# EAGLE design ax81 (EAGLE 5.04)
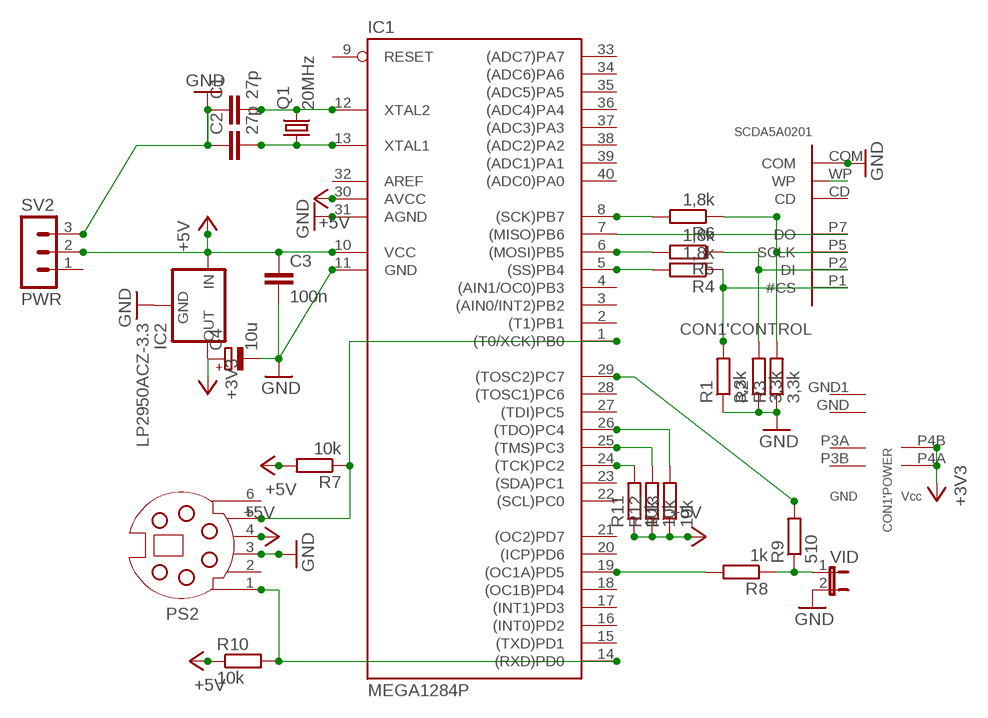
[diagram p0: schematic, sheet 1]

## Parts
C1  27p  C-EU025-025X050  [C025-025X050]
C2  27p  C-EU025-025X050  [C025-025X050]
C3  100n  C-EU025-025X050  [C025-025X050]
C4  10u  CPOL-EUE2.5-5  [E2,5-5]
CON1  SCDA5A0201  [SCDA5A0201]
IC1  MEGA1284P  MEGA32-P  [DIL40]
IC2  LP2950ACZ-3.3  [TO92]
PS2  MDSSV-BC06  [SSV-BC06]
Q1  20MHz  CRYSTALHC49U-V  [HC49U-V]
R1  3,3k  R-EU_0207/7  [0207/7]
R2  3,3k  R-EU_0207/7  [0207/7]
R3  3,3k  R-EU_0207/7  [0207/7]
R4  1,8k  R-EU_0207/7  [0207/7]
R5  1,8k  R-EU_0207/7  [0207/7]
R6  1,8k  R-EU_0207/7  [0207/7]
R7  10k  R-EU_0207/7  [0207/7]
R8  1k  R-EU_0207/7  [0207/7]
R9  510  R-EU_0207/7  [0207/7]
R10  10k  R-EU_0207/7  [0207/7]
R11  10k  R-EU_0207/7  [0207/7]
R12  10k  R-EU_0207/7  [0207/7]
R13  10k  R-EU_0207/7  [0207/7]
SV2  PWR  MA03-1  [MA03-1]
VID  JP1E  [JP1]

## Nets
+3V3: C4.+ CON1.P4A('POWER:VCC) CON1.P4B('POWER:VCC1) IC2.1(OUT)
+5V: C3.1 IC1.10(VCC) IC1.30(AVCC) IC2.3(IN) PS2.4 R7.2 R10.1 R11.1 R12.1 R13.1 SV2.2
GND: C1.1 C2.1 C3.2 C4.- CON1.COM('CONTROL:COM) IC1.11(GND) IC1.31(AGND) IC2.2(GND) PS2.3 R1.1 R2.1 R3.1 SV2.3 VID.2
N$1: C1.2 IC1.12(XTAL2) Q1.2
N$2: C2.2 IC1.13(XTAL1) Q1.1
N$3: IC1.19((OC1A)PD5) R8.2
N$4: IC1.5((SS)PB4) R4.2
N$5: IC1.6((MOSI)PB5) R5.2
N$6: IC1.8((SCK)PB7) R6.2
N$7: CON1.P1('CONTROL:#CS) R1.2 R4.1
N$8: CON1.P7('CONTROL:DO) IC1.7((MISO)PB6)
N$9: CON1.P2('CONTROL:DI) R2.2 R5.1
N$10: R8.1 R9.1 VID.1
N$11: IC1.29((TOSC2)PC7) R9.2
N$12: IC1.14((RXD)PD0) PS2.1 R10.2
N$13: IC1.1((T0/XCK)PB0) PS2.5 R7.1
N$14: IC1.24((TCK)PC2) R11.2
N$15: IC1.25((TMS)PC3) R12.2
N$16: IC1.26((TDO)PC4) R13.2
N$20: CON1.P5('CONTROL:SCLK) R3.2 R6.1
N$24: CON1.WP('CONTROL:WP)
Unconnected: CON1.CD('CONTROL:CD) IC1.2((T1)PB1) IC1.3((AIN0/INT2)PB2) IC1.4((AIN1/OC0)PB3) IC1.9(RESET) IC1.15((TXD)PD1) IC1.16((INT0)PD2) IC1.17((INT1)PD3) IC1.18((OC1B)PD4) IC1.20((ICP)PD6) IC1.21((OC2)PD7) IC1.22((SCL)PC0) IC1.23((SDA)PC1) IC1.27((TDI)PC5) IC1.28((TOSC1)PC6) IC1.32(AREF) IC1.33((ADC7)PA7) IC1.34((ADC6)PA6) IC1.35((ADC5)PA5) IC1.36((ADC4)PA4) IC1.37((ADC3)PA3) IC1.38((ADC2)PA2) IC1.39((ADC1)PA1) IC1.40((ADC0)PA0) PS2.2 PS2.6 SV2.1

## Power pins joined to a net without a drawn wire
GND: CON1.GND1('POWER:GND) CON1.GND('POWER:GND) CON1.P3A('POWER:GND) CON1.P3B('POWER:GND)

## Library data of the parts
C1-C3 = rcl:C-EU: CAPACITOR, European symbol
C4 = rcl:CPOL-EU: POLARIZED CAPACITOR, European symbol
CON1 = SCDA5A0201:SCDA5A0201: ALPS Connector for SDMemory Card SD-CARD SCDA5A0201 SPI -MODE
IC1 = atmel:MEGA32-P: MICROCONTROLLER 32 Kbytes FLASH 2 Kbytes SRAM 1 Kbytes EEPROM USART 8-channel 10 bit ADC Source: www.atmel.com .. doc2503.pdf
IC2 = v-reg:LP2950?*: Source: http://cache.national.com/ds/LP/LP2950.pdf
PS2 = con-yamaichi:MDSSV-BC06: YAMAICHI CONNECTOR
Q1 = crystal:CRYSTAL: CRYSTAL
R1-R13 = rcl:R-EU_: RESISTOR, European symbol
SV2 = con-lstb:MA03-1: PIN HEADER
VID = jumper:JP1E: JUMPER

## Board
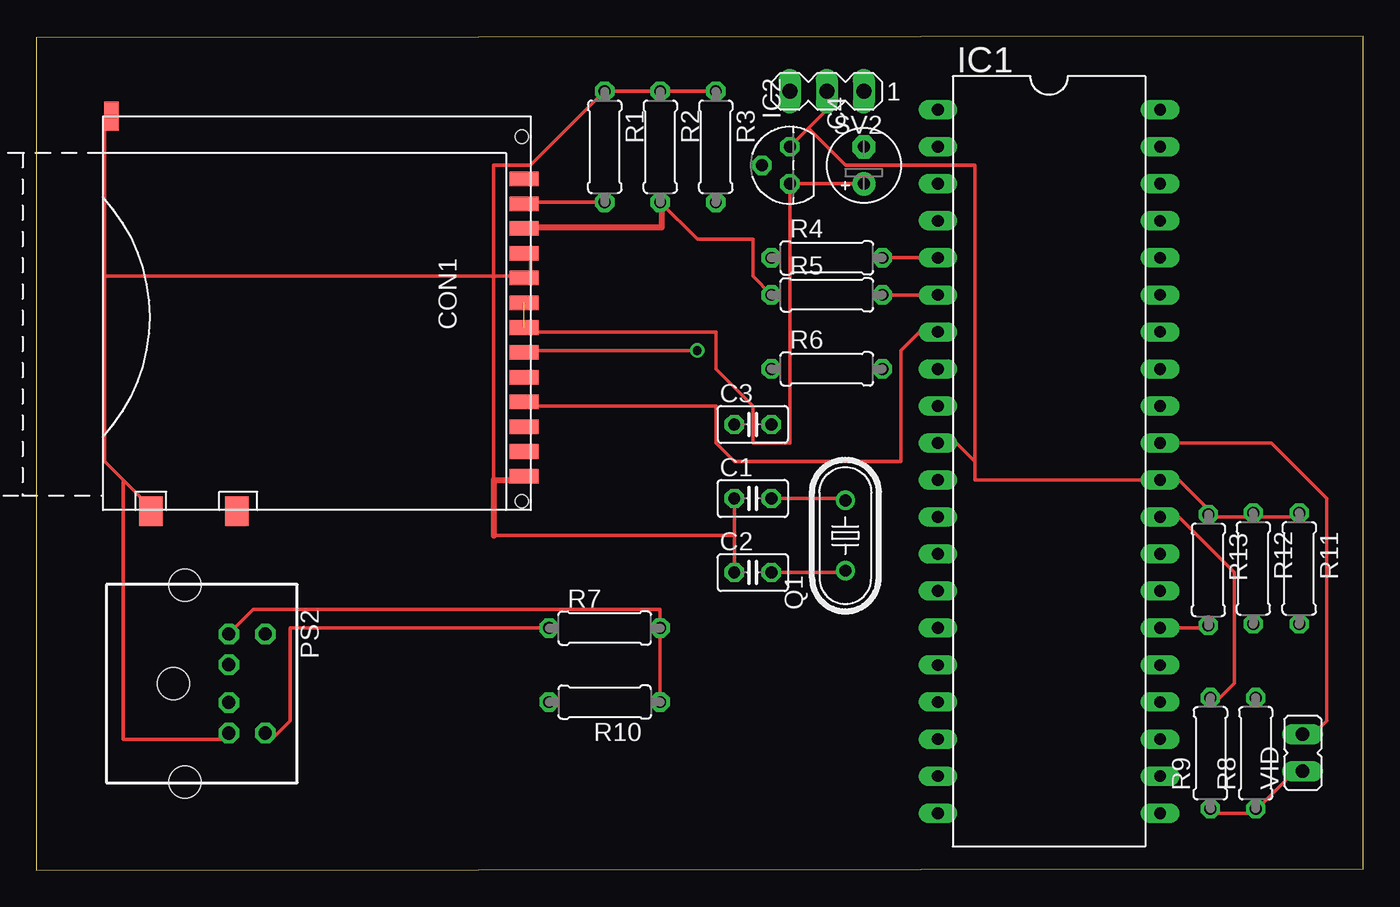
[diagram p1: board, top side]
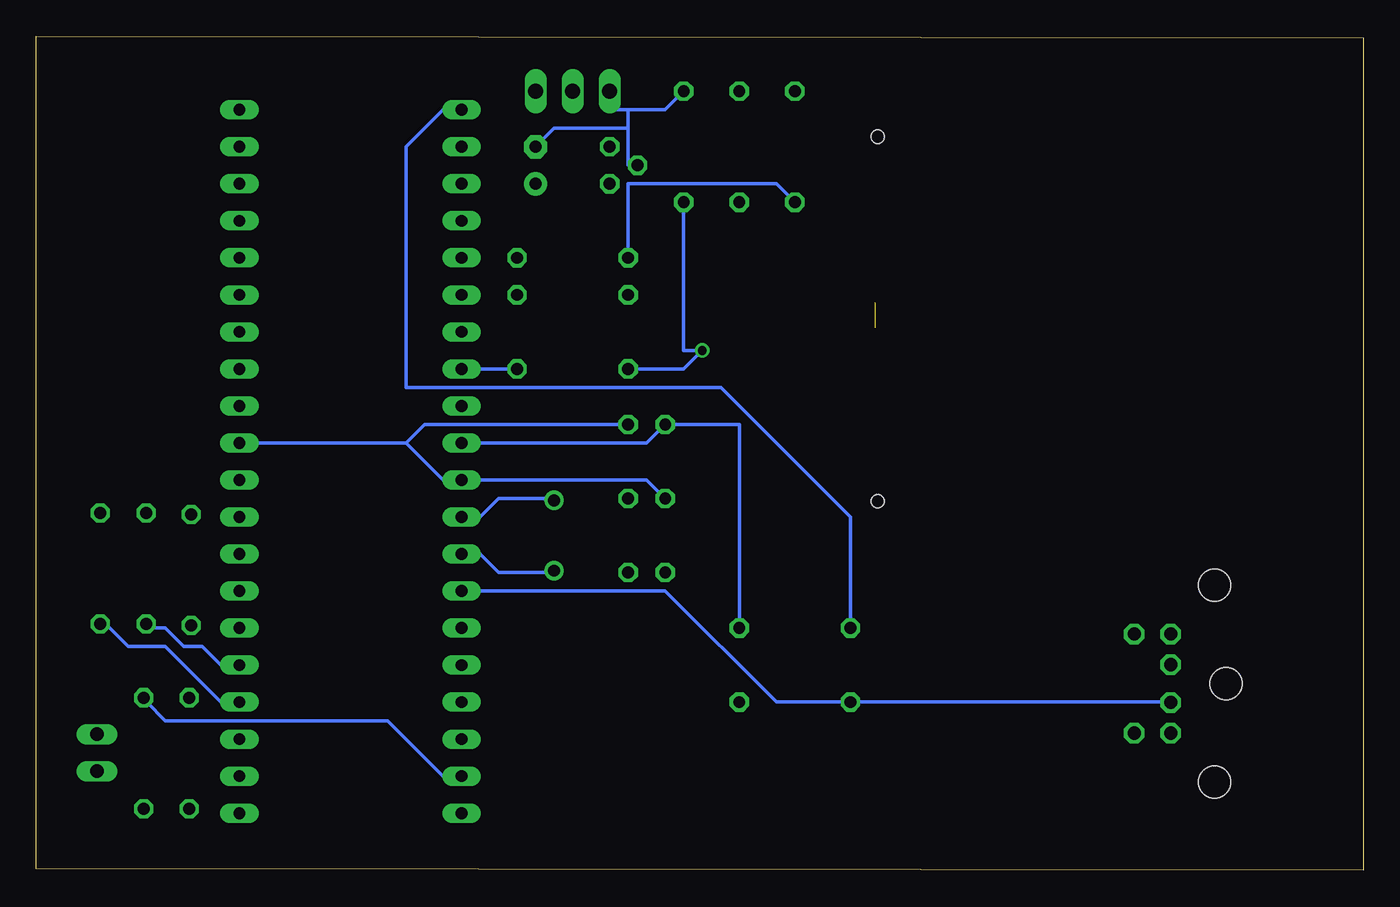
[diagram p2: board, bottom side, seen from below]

Size 91 x 57.2 mm. Coordinates in mm from the lower left corner, seen from the top.
Outline: 0,0 91,0.1 91,57.2 0,57.1 0,0
Copper layers (1*16): Top 0.035mm / dielectric 1.5mm / Bottom 0.035mm
Design rules "default": minimum track width 10mil, minimum drill 24mil, track to track 8mil, track to pad 8mil, pad to pad 8mil, via to via 8mil, smd to smd 8mil, copper to edge 40mil, drill to drill 8mil, minimum pad ring 10mil, minimum via ring 8mil, stop-mask expansion 4mil, vias tented up to drill 0mil, thermal gap 10mil

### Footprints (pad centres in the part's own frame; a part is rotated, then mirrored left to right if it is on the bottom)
C025-025X050 = drill 0.813 octagon: 1 -1.27,0; 2 1.27,0
E2,5-5 = drill 0.813 pad 1.6 round: + -1.27,0 | drill 0.813 pad 1.6 octagon: - 1.27,0
SCDA5A0201 = smd 1 x 2: CD 9.475,-0.45; COM 11.175,-0.45; P1 -7.525,-0.45; P2 -5.825,-0.45; P3A -4.125,-0.45; P3B -2.425,-0.45; P4A -0.725,-0.45; P4B 0.975,-0.45; P5 2.675,-0.45; P6 4.375,-0.45; P7 6.075,-0.45; P8 7.775,-0.45; P9 -9.225,-0.45 | smd 2 x 1.6: GND 13.575,-26.05; WP 13.575,-20.15 | smd 2 x 1: GND1 -13.525,-28.75 | hole 0.9: -12.125,-0.6; 12.875,-0.6
DIL40 = drill 0.813 long: 1 -24.13,-7.62; 2 -21.59,-7.62; 3 -19.05,-7.62; 4 -16.51,-7.62; 5 -13.97,-7.62; 6 -11.43,-7.62; 7 -8.89,-7.62; 8 -6.35,-7.62; 9 -3.81,-7.62; 10 -1.27,-7.62; 11 1.27,-7.62; 12 3.81,-7.62; 13 6.35,-7.62; 14 8.89,-7.62; 15 11.43,-7.62; 16 13.97,-7.62; 17 16.51,-7.62; 18 19.05,-7.62; 19 21.59,-7.62; 20 24.13,-7.62; 21 24.13,7.62; 22 21.59,7.62; 23 19.05,7.62; 24 16.51,7.62; 25 13.97,7.62; 26 11.43,7.62; 27 8.89,7.62; 28 6.35,7.62; 29 3.81,7.62; 30 1.27,7.62; 31 -1.27,7.62; 32 -3.81,7.62; 33 -6.35,7.62; 34 -8.89,7.62; 35 -11.43,7.62; 36 -13.97,7.62; 37 -16.51,7.62; 38 -19.05,7.62; 39 -21.59,7.62; 40 -24.13,7.62
TO92 = drill 0.813 octagon: 1 -1.27,0; 2 0,1.905; 3 1.27,0
SSV-BC06 = drill 0.9 octagon: 1 1.3,8.5; 2 -1.3,8.5; 3 3.4,8.5; 4 -3.4,8.5; 5 3.4,11; 6 -3.4,11 | hole 2.2: -6.75,5.5; 0,4.7; 6.75,5.5
HC49U-V = drill 0.813 round: 1 -2.413,0; 2 2.413,0
0207/7 = drill 0.813 octagon: 1 -3.81,0; 2 3.81,0
MA03-1 = drill 1.016 long: 1 -2.54,0; 2 0,0; 3 2.54,0
JP1 = drill 0.914 long: 1 0,-1.27; 2 0,1.27

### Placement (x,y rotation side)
C1  49.14,25.5 0 top
C2  49.14,20.42 0 top
C3  49.14,30.58 0 top
C4  56.76,48.36 90 top
CON1  33.9,38.2 270 top
IC1  69.46,28.04 270 top
IC2  51.68,48.36 90 top
PS2  4.69,12.8 270 top
Q1  55.49,22.96 90 top
R1  38.98,49.63 270 top
R2  42.79,49.63 270 top
R3  46.6,49.63 270 top
R4  54.22,42.01 0 top
R5  54.22,39.47 0 top
R6  54.22,34.39 0 top
R7  38.98,16.61 0 top
R8  83.64,8.02 90 top
R9  80.53,8.02 90 top
R10  38.98,11.53 180 top
R11  86.62,20.7 270 top
R12  83.47,20.7 270 top
R13  80.39,20.6 270 top
SV2  54.22,53.44 180 top
VID  86.85,8.06 0 top

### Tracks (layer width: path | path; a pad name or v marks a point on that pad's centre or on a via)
+3V3  (1 unrouted)
  Top 0.254: CON1.P4B 33.9,36.93 46.6,36.93 46.6,34.39 49.14,31.85 49.14,29.31 51.68,29.31 IC2.1 C4.+
+5V
  Top 0.254: R10.1 R7.2 42.79,17.88 14.85,17.88 13.58,16.61 PS2.4 | 52.95,50.9 54.22,52.17 SV2.2 | 52.95,50.9 IC2.3 | 64.38,28.04 64.38,26.77 IC1.30 78.35,26.77 80.89,24.23 | 64.38,28.04 63.11,29.31 IC1.10 | 52.95,50.9 55.49,48.36 64.38,48.36 64.38,28.04 | 80.89,24.23 83.43,24.23 | 83.43,24.23 85.97,24.23 R11.1 | 83.43,24.23 R12.1 | 80.89,24.23 R13.1
  Bottom 0.254: IC1.10 49.14,29.31 C3.1 42.79,30.58 R7.2
GND
  Top 0.254: 47.87,22.96 C1.1 | 47.87,22.96 C2.1 | R3.1 R2.1 R1.1 33.9,48.36 31.36,48.36 31.36,40.74 | CON1.P3A 33.9,42.01 33.9,40.74 CON1.P3B 32.63,40.74 31.36,40.74 | 5.96,26.77 4.69,28.04 4.69,40.74 | 5.96,26.77 7.23,25.5 CON1.GND | 4.69,40.74 4.69,50.9 CON1.GND1 | 4.69,40.74 31.36,40.74 | 5.96,26.77 5.96,8.99 13.58,8.99 PS2.3 | 31.36,22.96 47.87,22.96 | 31.36,40.74 31.36,26.77 | VID.2 87.24,8.99 88.51,10.26 88.51,25.5 84.7,29.31 IC1.31
  Top 0.406: CON1.COM 33.45,26.77 31.36,26.77 31.36,22.96
  Bottom 0.254: 65.65,29.31 63.11,26.77 IC1.11 49.14,26.77 C1.1 | 65.65,29.31 IC1.31 | C3.2 64.38,30.58 65.65,29.31 | 50.41,52.17 50.41,50.9 | 50.41,50.9 50.41,48.36 IC2.2 | 50.41,52.17 51.68,52.17 SV2.3 | C4.- 55.49,50.9 50.41,50.9 | R3.1 47.87,52.17 50.41,52.17
N$1
  Top 0.254: C1.2 55.49,25.5 Q1.2
  Bottom 0.254: IC1.12 60.57,24.23 59.3,25.5 55.49,25.5 Q1.2
N$2
  Top 0.254: C2.2 55.49,20.42 Q1.1
  Bottom 0.254: IC1.13 60.57,21.69 59.3,20.42 55.49,20.42 Q1.1
N$3
  Bottom 0.254: IC1.19 63.11,6.45 66.92,10.26 82.16,10.26 83.43,11.53 R8.2
N$4
  Top 0.254: R4.2 IC1.5
N$5
  Top 0.254: R5.2 IC1.6
N$6
  Bottom 0.254: R6.2 IC1.8
N$7
  Top 0.254: R1.2 33.9,45.82 CON1.P1
  Bottom 0.254: R4.1 50.41,47.09 40.25,47.09 R1.2
N$8
  Top 0.254: CON1.P7 33.9,31.85 46.6,31.85 46.6,29.31 47.87,28.04 59.3,28.04 59.3,35.66 60.57,36.93 IC1.7
N$9
  Top 0.254: R2.2 45.33,43.28 49.14,43.28 49.14,40.74 R5.1
  Top 0.406: R2.2 42.9,45.82 42.9,44.1 33.45,44.1 CON1.P2
N$10
  Top 0.254: 83.43,3.91 80.89,3.91 R9.1 | 83.43,3.91 85.97,6.45 VID.1 | 83.43,3.91 R8.1
N$11
  Top 0.254: R9.2 80.89,11.53 82.16,12.8 82.16,20.42 78.35,24.23 IC1.29
N$12
  Bottom 0.254: PS2.1 13.58,11.53 R10.2 40.25,11.53 47.87,19.15 IC1.14
N$13
  Top 0.254: R7.1 17.39,16.61 17.39,10.26 16.12,8.99 PS2.5
  Bottom 0.254: R7.1 35.17,24.23 44.06,33.12 65.65,33.12 65.65,49.63 63.11,52.17 IC1.1
N$14
  Bottom 0.254: IC1.24 78.35,11.53 82.16,15.34 84.7,15.34 85.97,16.61 R11.2
N$15
  Bottom 0.254: IC1.25 78.35,14.07 79.62,15.34 80.89,15.34 82.16,16.61 83.43,16.61 R12.2
N$16
  Top 0.254: IC1.26 80.89,16.61 R13.2
N$20  (via drill 0.61)
  Top 0.254: v45.33,35.66 33.9,35.66 CON1.P5
  Bottom 0.254: R6.1 46.6,34.39 v45.33,35.66 46.6,35.66 R3.2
